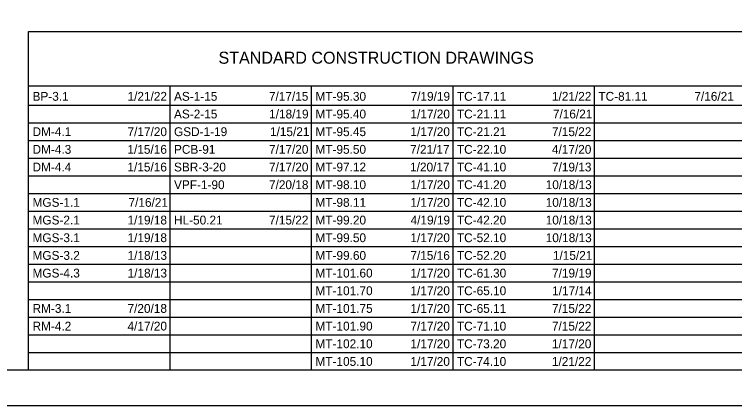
# Model space of a CAD drawing. Extents: x 0 to 34, y 0 to 22.
# Drawn here: x 9.95 to 20.13, y 0 to 5.53 of the extents above; entities that cross this region are included whole.
import ezdxf

# ---------------------------------------------------------------- set-up
doc = ezdxf.new("R2010")
doc.units = 0
for name, color, linetype in [('GM_X_Adjacent_County', 7, 'Continuous'), ('GM_X_County', 7, 'Continuous'), ('GM_X_Section', 7, 'Continuous'), ('GM_X_Township', 7, 'Continuous')]:
    doc.layers.add(name, color=color, linetype=linetype)

msp = doc.modelspace()

# ---------------------------------------------------------------- linework, layer by layer
at = {"layer": 'GM_X_County'}
msp.add_lwpolyline([(1.5, 21.5), (33.5, 21.5), (33.5, 0.5), (1.5, 0.5)], close=True, dxfattribs=at)
at = {"layer": 'GM_X_Section'}
msp.add_lwpolyline([(0, 0), (34, 0), (34, 22), (0, 22)], close=True, dxfattribs=at)
at = {"layer": 'GM_X_Township'}
for p, q in [((10.15, 5.292), (23.6, 5.292)), ((10.15, 0.5), (10.15, 5.292)), ((10.15, 4.521), (23.6, 4.521)), ((12.15, 0.5), (12.15, 4.521)), ((14.15, 0.5), (14.15, 4.521)), ((16.15, 0.5), (16.15, 4.521)), ((18.15, 0.5), (18.15, 4.521)), ((10.15, 4.25), (23.6, 4.25)), ((10.15, 4), (23.6, 4)), ((10.15, 3.75), (23.6, 3.75)), ((10.15, 3.5), (23.6, 3.5)), ((10.15, 3.25), (23.6, 3.25)), ((10.15, 3), (23.6, 3)), ((10.15, 2.75), (23.6, 2.75)), ((10.15, 2.5), (23.6, 2.5)), ((10.15, 2.25), (23.6, 2.25)), ((10.15, 2), (23.6, 2)), ((10.15, 1.75), (23.6, 1.75)), ((10.15, 1.5), (23.6, 1.5)), ((10.15, 1.25), (23.6, 1.25)), ((10.15, 1), (23.6, 1)), ((10.15, 0.75), (23.6, 0.75))]:
    msp.add_line(p, q, dxfattribs=at)

# ---------------------------------------------------------------- texts
at = {"layer": 'GM_X_Adjacent_County'}
msp.add_text('STANDARD CONSTRUCTION DRAWINGS', height=0.17, dxfattribs=at).set_placement((12.834, 4.836))
at = {"layer": 'GM_X_Township'}
for s, p in [('BP-3.1', (10.205, 4.312)), ('1/21/22', (11.548, 4.312)), ('AS-1-15', (12.205, 4.312)), ('7/17/15', (13.547, 4.312)), ('MT-95.30', (14.205, 4.312)), ('7/19/19', (15.55, 4.312)), ('TC-17.11', (16.205, 4.312)), ('1/21/22', (17.548, 4.312)), ('TC-81.11', (18.205, 4.312)), ('7/16/21', (19.562, 4.312)), ('AS-2-15', (12.205, 4.062)), ('1/18/19', (13.55, 4.062)), ('MT-95.40', (14.205, 4.062)), ('1/17/20', (15.548, 4.062)), ('TC-21.11', (16.205, 4.062)), ('7/16/21', (17.562, 4.062)), ('DM-4.1', (10.205, 3.812)), ('7/17/20', (11.548, 3.812)), ('GSD-1-19', (12.205, 3.812)), ('1/15/21', (13.562, 3.812)), ('MT-95.45', (14.205, 3.812)), ('1/17/20', (15.548, 3.812)), ('TC-21.21', (16.205, 3.812)), ('7/15/22', (17.548, 3.812)), ('DM-4.3', (10.205, 3.562)), ('1/15/16', (11.547, 3.562)), ('PCB-91', (12.205, 3.562)), ('7/17/20', (13.548, 3.562)), ('MT-95.50', (14.205, 3.562)), ('7/21/17', (15.543, 3.562)), ('TC-22.10', (16.205, 3.562)), ('4/17/20', (17.548, 3.562)), ('DM-4.4', (10.205, 3.312)), ('1/15/16', (11.547, 3.312)), ('SBR-3-20', (12.205, 3.312)), ('7/17/20', (13.548, 3.312)), ('MT-97.12', (14.205, 3.312)), ('1/20/17', (15.543, 3.312)), ('TC-41.10', (16.205, 3.312)), ('7/19/13', (17.549, 3.312)), ('VPF-1-90', (12.205, 3.062)), ('7/20/18', (13.548, 3.062)), ('MT-98.10', (14.205, 3.062)), ('1/17/20', (15.548, 3.062)), ('TC-41.20', (16.205, 3.062)), ('10/18/13', (17.46, 3.062)), ('MGS-1.1', (10.205, 2.812)), ('7/16/21', (11.562, 2.812)), ('MT-98.11', (14.205, 2.812)), ('1/17/20', (15.548, 2.812)), ('TC-42.10', (16.205, 2.812)), ('10/18/13', (17.46, 2.812)), ('MGS-2.1', (10.205, 2.562)), ('1/19/18', (11.548, 2.562)), ('HL-50.21', (12.205, 2.562)), ('7/15/22', (13.548, 2.562)), ('MT-99.20', (14.205, 2.562)), ('4/19/19', (15.55, 2.562)), ('TC-42.20', (16.205, 2.562)), ('10/18/13', (17.46, 2.562)), ('1/19/18', (11.548, 2.312)), ('1/17/20', (15.548, 2.312)), ('10/18/13', (17.46, 2.312)), ('MGS-3.1', (10.205, 2.312)), ('MT-99.50', (14.205, 2.312)), ('TC-52.10', (16.205, 2.312)), ('MGS-3.2', (10.205, 2.062)), ('1/18/13', (11.549, 2.062)), ('MT-99.60', (14.205, 2.062)), ('7/15/16', (15.547, 2.062)), ('TC-52.20', (16.205, 2.062)), ('1/15/21', (17.562, 2.062)), ('MGS-4.3', (10.205, 1.812)), ('1/18/13', (11.549, 1.812)), ('MT-101.60', (14.205, 1.812)), ('1/17/20', (15.548, 1.812)), ('TC-61.30', (16.205, 1.812)), ('7/19/19', (17.55, 1.812)), ('MT-101.70', (14.205, 1.562)), ('1/17/20', (15.548, 1.562)), ('TC-65.10', (16.205, 1.562)), ('1/17/14', (17.551, 1.562)), ('RM-3.1', (10.205, 1.312)), ('7/20/18', (11.548, 1.312)), ('MT-101.75', (14.205, 1.312)), ('1/17/20', (15.548, 1.312)), ('TC-65.11', (16.205, 1.312)), ('7/15/22', (17.548, 1.312)), ('RM-4.2', (10.205, 1.062)), ('4/17/20', (11.548, 1.062)), ('MT-101.90', (14.205, 1.062)), ('7/17/20', (15.548, 1.062)), ('TC-71.10', (16.205, 1.062)), ('7/15/22', (17.548, 1.062)), ('MT-102.10', (14.205, 0.812)), ('1/17/20', (15.548, 0.812)), ('TC-73.20', (16.205, 0.812)), ('1/17/20', (17.548, 0.812)), ('MT-105.10', (14.205, 0.562)), ('1/17/20', (15.548, 0.562)), ('TC-74.10', (16.205, 0.562)), ('1/21/22', (17.548, 0.562))]:
    msp.add_text(s, height=0.125, dxfattribs=at).set_placement(p)

doc.saveas('drawing.dxf')
